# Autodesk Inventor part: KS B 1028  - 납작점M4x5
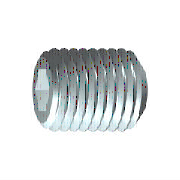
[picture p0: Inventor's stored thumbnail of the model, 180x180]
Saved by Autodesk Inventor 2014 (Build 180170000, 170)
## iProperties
IsCustomPart: 0
Created: 2009-02
Part Number: KS B 1028  - 납작점M4x5
Material: Steel, Mild
Description: 6각 소켓 머리 없는 멈춤 나사
Document SubType Name: Modeling
Standard: KS B 1028
Designer: KYOUNG IL JANG
Standards Organization: KS
Language: ko-KR
Size Designation: 납작점M4x5
Categories: <MemberInstance><Categories><Category DisplayName="조임쇠" InternalName="e4da775c-781d-43d5-af7c-5136215cf5a6" Mnemonic="FSTN"><Category DisplayName="볼트" InternalN
Density: 7.86 g/cm^3
Appearance: Metal-Steel
Mass: 0.401763 g
Surface Area: 0.994256 cm^2
Volume: 0.0511149 cm^3
Author: KYOUNG IL JANG
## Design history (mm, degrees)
sketch "스케치1"
  geometry: L1 (0, 0)-(1.833, 0); L2 (5, 1.155)-(5, 2); L3 (5, 2)-(0, 2); L4 (5, 1.155)-(2.5, 1.155); L5 (2.5, 1.155)-(1.833, 0); L6 (0, -0.4)-(0, 2.4) reference; L7 (0, 2)-(0, 0)
  constraints: 13 end point, 3 parallel, 1 collinear, 1 perpendicular, 1 point on line
  dimensions: "d0" = 2.5 distance of L2.start L4.end (= INTI); "d1" = 60 deg angle of L5 L1; "d2" = 4 diameter of L3 L1 (= NND); "d3" = 2.3094 diameter of L4 L1 (= 1.1547 x SW); "d5" = 5 distance from line of L2 L3.end (= NLG)
revolve "본체" sketch "스케치1" stored, may be unused: angle "d6" = 90 deg
sketch "스케치2"
  geometry: L1 (-0.577, 1)-(0.577, 1); L2 (0.577, 1)-(1.155, 0); L3 (1.155, 0)-(0.577, -1); L4 (0.577, -1)-(-0.577, -1); L5 (-0.577, -1)-(-1.155, 0); L6 (-1.155, 0)-(-0.577, 1); A1 r 1.155 centre (0, 0) between (-0.577, 1) and (0.577, 1) reference; 2 further points
  constraints: 12 end point, 2 point on circle, 1 coincident, 1 horizontal, 11 other
extrude "슬롯" join sketch "스케치2" taper "d9" = 0 deg; stored distance "d21" = 10
workaxis "Work Axis1"
workplane "Work Plane1"
body "Solid1"
chamfer "모따기1" distance "d7" = 0.42941 (= -0.5 x GD1 + 0.5 x NND); stored, may be unused: angle "d8" = 45 deg (= FAWI), second distance "d29" = 0.42941 (= -0.5 x GD1 + 0.5 x NND)
feature "스레드" dims "d11" = 5 (= NLG), "d12" = 0
chamfer "모따기2" distance "d13" = 0.42941 (= -0.5 x GD1 + 0.5 x NND); stored, may be unused: angle "d14" = 45 deg (= FAWI), second distance "d30" = 0.42941 (= -0.5 x GD1 + 0.5 x NND)
other parameters: "NND" = 4 [user parameter; used in 5 equation terms], "NLG" = 5 [user parameter; used in 2 equation terms], "INTI" = 2.5 [user parameter; used in 1 equation term], "FAWI" = 45 deg [user parameter; used in 2 equation terms], "SW" = 2 [user parameter; used in 2 equation terms], "GD1" = 3.14117 (= THREADDIA - 1.2269 x PTC) [user parameter; used in 4 equation terms], "d4" = 0, "FAWI1" = 45 deg [user parameter], "d15" = 0, "d31" = 0, "GUL" = 0.42941 (= 0.61345 x PTC) [user parameter], "SPD" = 2.5 [user parameter], "TPU" = 14.28571 (computed from PTC) [user parameter], "TOA" = 30 deg [user parameter], "THREADDIA" = 4 [user parameter; used in 1 equation term], "PTC" = 0.7 [user parameter; used in 4 equation terms], "GAL" = 0.42941 (= 0.61345 x PTC) [user parameter], "E0" = 2.31 (= 1.155 x SW) [user parameter]
